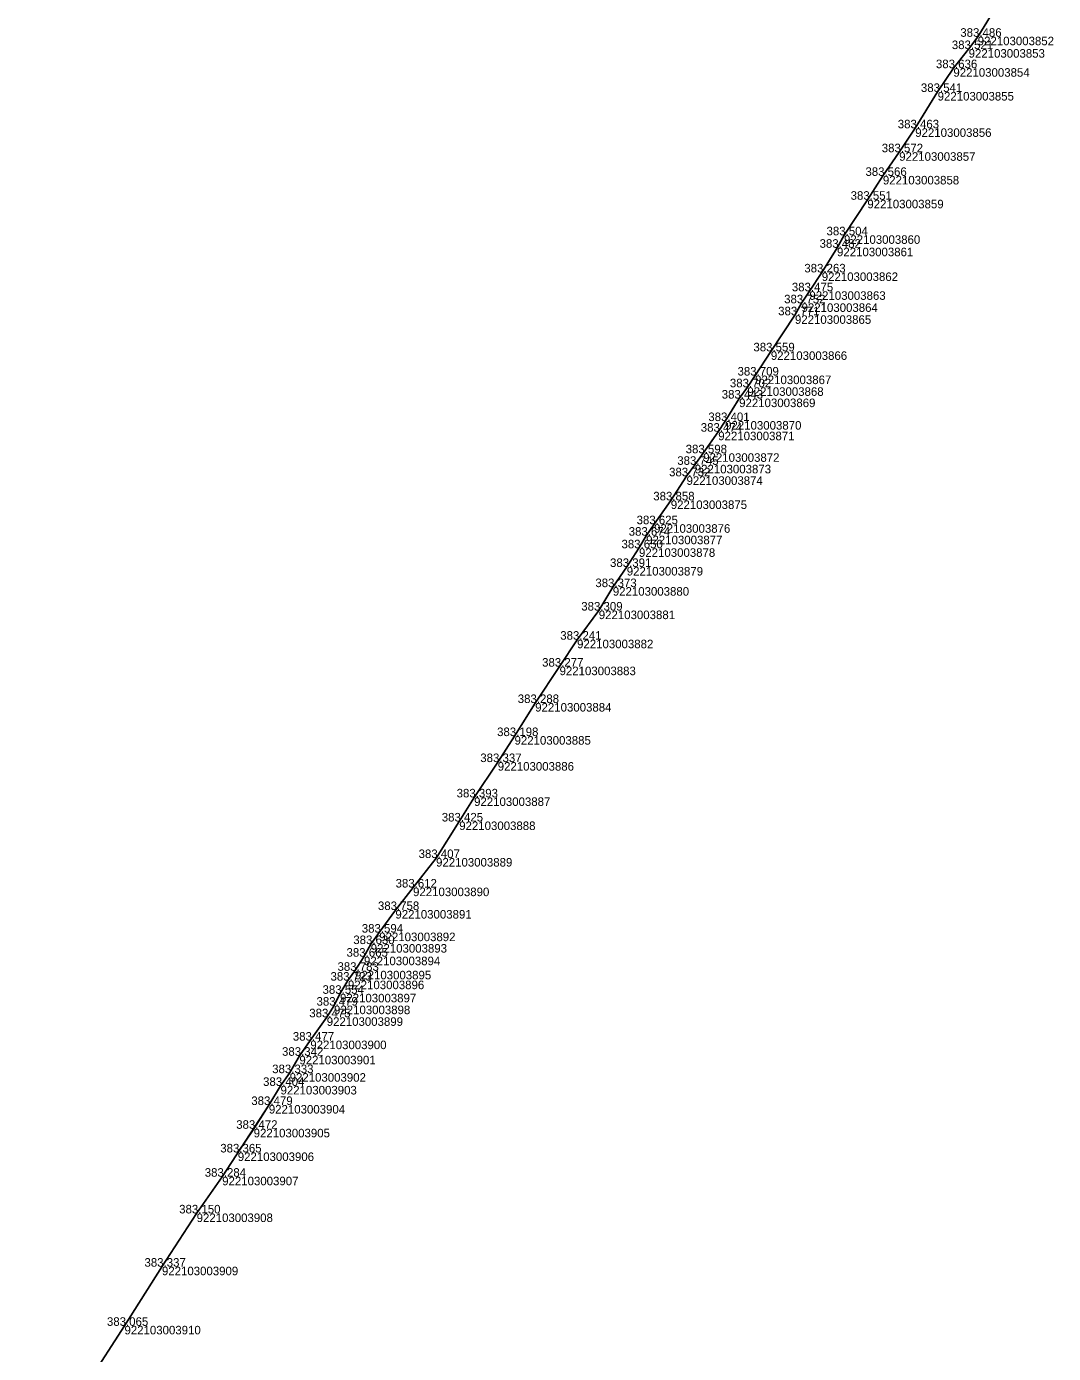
# Model space of a CAD drawing. Extents: x -771047 to -756200, y -1053876 to -1046520.
# Drawn here: x -756960.7 to -756816.5, y -1047253.2 to -1047067 of the extents above; entities that cross this region are included whole.
import ezdxf

# ---------------------------------------------------------------- set-up
doc = ezdxf.new("R2010")
doc.units = 0
for name, color, linetype in [('Vrstva 32', 7, 'Continuous'), ('Vrstva 60', 7, 'Continuous'), ('Vrstva 61', 7, 'Continuous')]:
    doc.layers.add(name, color=color, linetype=linetype)

msp = doc.modelspace()

# ---------------------------------------------------------------- linework, layer by layer
at = {"layer": 'Vrstva 32'}
for points in [[(-756825.38, -1047065.54), (-756827.16, -1047068.41), (-756828.44, -1047070.14), (-756830.58, -1047072.82), (-756832.79, -1047076.16), (-756835.94, -1047081.26), (-756838.19, -1047084.62), (-756840.48, -1047087.94), (-756842.66, -1047091.29), (-756845.94, -1047096.28), (-756846.92, -1047098.03)], [(-756846.92, -1047098.03), (-756849.06, -1047101.49), (-756850.8, -1047104.14)], [(-756850.8, -1047104.14), (-756851.9, -1047105.83), (-756852.83, -1047107.51), (-756856.21, -1047112.57), (-756858.43, -1047115.97), (-756859.51, -1047117.62), (-756860.66, -1047119.2)], [(-756860.66, -1047119.2), (-756862.63, -1047122.36), (-756863.6, -1047123.85), (-756865.71, -1047126.88)], [(-756865.71, -1047126.88), (-756866.89, -1047128.5), (-756868.05, -1047130.11), (-756870.26, -1047133.49), (-756872.61, -1047136.84), (-756873.72, -1047138.45), (-756874.73, -1047140.22)], [(-756874.73, -1047140.22), (-756876.44, -1047142.84), (-756878.4, -1047145.67), (-756880.37, -1047148.96), (-756883.42, -1047153.05), (-756885.88, -1047156.83), (-756889.3, -1047161.94), (-756892.2, -1047166.58), (-756894.56, -1047170.23)], [(-756894.56, -1047170.23), (-756897.88, -1047175.19), (-756899.97, -1047178.57), (-756903.22, -1047183.7)], [(-756903.22, -1047183.7), (-756906.45, -1047187.84)], [(-756906.45, -1047187.84), (-756908.93, -1047191)], [(-756908.93, -1047191), (-756911.2, -1047194.17)], [(-756911.2, -1047194.17), (-756912.39, -1047195.78), (-756913.34, -1047197.55), (-756914.61, -1047199.53), (-756915.59, -1047200.91), (-756916.71, -1047202.76), (-756917.55, -1047204.42), (-756918.57, -1047206.06), (-756920.88, -1047209.33)], [(-756920.88, -1047209.33), (-756922.41, -1047211.46), (-756923.78, -1047213.9), (-756925.06, -1047215.69), (-756926.7, -1047218.37), (-756933.25, -1047228.44), (-756936.84, -1047233.59), (-756941.71, -1047241.07), (-756946.97, -1047249.37), (-756951.98, -1047257.13), (-756957.27, -1047264.84), (-756960.72, -1047269.53)], [(-756926.7, -1047218.37), (-756928.83, -1047221.71), (-756931.06, -1047225.03)]]:
    msp.add_lwpolyline(points, dxfattribs=at)
at = {"layer": 'Vrstva 60'}
for p, q in [((-756827.16, -1047068.41), (-756827.16, -1047068.41)), ((-756828.44, -1047070.14), (-756828.44, -1047070.14)), ((-756830.58, -1047072.82), (-756830.58, -1047072.82)), ((-756832.79, -1047076.16), (-756832.79, -1047076.16)), ((-756835.94, -1047081.26), (-756835.94, -1047081.26)), ((-756838.19, -1047084.62), (-756838.19, -1047084.62)), ((-756840.48, -1047087.94), (-756840.48, -1047087.94)), ((-756842.66, -1047091.29), (-756842.66, -1047091.29)), ((-756845.94, -1047096.28), (-756845.94, -1047096.28)), ((-756846.92, -1047098.03), (-756846.92, -1047098.03)), ((-756849.06, -1047101.49), (-756849.06, -1047101.49)), ((-756850.8, -1047104.14), (-756850.8, -1047104.14)), ((-756852.83, -1047107.51), (-756852.83, -1047107.51)), ((-756851.9, -1047105.83), (-756851.9, -1047105.83)), ((-756856.21, -1047112.57), (-756856.21, -1047112.57)), ((-756858.43, -1047115.97), (-756858.43, -1047115.97)), ((-756859.51, -1047117.62), (-756859.51, -1047117.62)), ((-756860.66, -1047119.2), (-756860.66, -1047119.2)), ((-756862.63, -1047122.36), (-756862.63, -1047122.36)), ((-756863.6, -1047123.85), (-756863.6, -1047123.85)), ((-756865.71, -1047126.88), (-756865.71, -1047126.88)), ((-756866.89, -1047128.5), (-756866.89, -1047128.5)), ((-756868.05, -1047130.11), (-756868.05, -1047130.11)), ((-756870.26, -1047133.49), (-756870.26, -1047133.49)), ((-756872.61, -1047136.84), (-756872.61, -1047136.84)), ((-756873.72, -1047138.45), (-756873.72, -1047138.45)), ((-756874.73, -1047140.22), (-756874.73, -1047140.22)), ((-756876.44, -1047142.84), (-756876.44, -1047142.84)), ((-756878.4, -1047145.67), (-756878.4, -1047145.67)), ((-756880.37, -1047148.96), (-756880.37, -1047148.96)), ((-756883.42, -1047153.05), (-756883.42, -1047153.05)), ((-756885.88, -1047156.83), (-756885.88, -1047156.83)), ((-756889.3, -1047161.94), (-756889.3, -1047161.94)), ((-756892.2, -1047166.58), (-756892.2, -1047166.58)), ((-756894.56, -1047170.23), (-756894.56, -1047170.23)), ((-756897.88, -1047175.19), (-756897.88, -1047175.19)), ((-756899.97, -1047178.57), (-756899.97, -1047178.57)), ((-756903.22, -1047183.7), (-756903.22, -1047183.7)), ((-756906.45, -1047187.84), (-756906.45, -1047187.84)), ((-756908.93, -1047191), (-756908.93, -1047191)), ((-756911.2, -1047194.17), (-756911.2, -1047194.17)), ((-756912.39, -1047195.78), (-756912.39, -1047195.78)), ((-756913.34, -1047197.55), (-756913.34, -1047197.55)), ((-756914.61, -1047199.53), (-756914.61, -1047199.53)), ((-756915.59, -1047200.91), (-756915.59, -1047200.91)), ((-756917.55, -1047204.42), (-756917.55, -1047204.42)), ((-756916.71, -1047202.76), (-756916.71, -1047202.76)), ((-756918.57, -1047206.06), (-756918.57, -1047206.06)), ((-756920.88, -1047209.33), (-756920.88, -1047209.33)), ((-756922.41, -1047211.46), (-756922.41, -1047211.46)), ((-756925.06, -1047215.69), (-756925.06, -1047215.69)), ((-756923.78, -1047213.9), (-756923.78, -1047213.9)), ((-756926.7, -1047218.37), (-756926.7, -1047218.37)), ((-756928.83, -1047221.71), (-756928.83, -1047221.71)), ((-756931.06, -1047225.03), (-756931.06, -1047225.03)), ((-756933.25, -1047228.44), (-756933.25, -1047228.44)), ((-756936.84, -1047233.59), (-756936.84, -1047233.59)), ((-756941.71, -1047241.07), (-756941.71, -1047241.07)), ((-756946.97, -1047249.37), (-756946.97, -1047249.37))]:
    msp.add_line(p, q, dxfattribs=at)

# ---------------------------------------------------------------- texts
for s, p in [('922103003852', (-756827.16, -1047069.6)), ('922103003853', (-756828.44, -1047071.34)), ('922103003854', (-756830.58, -1047074.02)), ('922103003855', (-756832.79, -1047077.36)), ('922103003856', (-756835.94, -1047082.46)), ('922103003857', (-756838.19, -1047085.82)), ('922103003858', (-756840.48, -1047089.14)), ('922103003859', (-756842.66, -1047092.49)), ('922103003860', (-756845.94, -1047097.48)), ('922103003861', (-756846.92, -1047099.22)), ('922103003862', (-756849.06, -1047102.69)), ('922103003864', (-756851.9, -1047107.03)), ('922103003863', (-756850.8, -1047105.34)), ('922103003865', (-756852.83, -1047108.71)), ('922103003866', (-756856.21, -1047113.77)), ('922103003867', (-756858.43, -1047117.17)), ('922103003868', (-756859.51, -1047118.82)), ('922103003869', (-756860.66, -1047120.4)), ('922103003870', (-756862.63, -1047123.56)), ('922103003871', (-756863.6, -1047125.05)), ('922103003872', (-756865.71, -1047128.08)), ('922103003873', (-756866.89, -1047129.7)), ('922103003874', (-756868.05, -1047131.31)), ('922103003875', (-756870.26, -1047134.7)), ('922103003876', (-756872.61, -1047138.04)), ('922103003877', (-756873.72, -1047139.65)), ('922103003878', (-756874.73, -1047141.42)), ('922103003879', (-756876.44, -1047144.04)), ('922103003880', (-756878.4, -1047146.87)), ('922103003881', (-756880.37, -1047150.16)), ('922103003882', (-756883.42, -1047154.25)), ('922103003883', (-756885.88, -1047158.03)), ('922103003884', (-756889.3, -1047163.14)), ('922103003885', (-756892.2, -1047167.78)), ('922103003886', (-756894.56, -1047171.43)), ('922103003887', (-756897.88, -1047176.39)), ('922103003888', (-756899.97, -1047179.77)), ('922103003889', (-756903.22, -1047184.9)), ('922103003890', (-756906.45, -1047189.05)), ('922103003891', (-756908.93, -1047192.2)), ('922103003892', (-756911.2, -1047195.37)), ('922103003893', (-756912.39, -1047196.98)), ('922103003894', (-756913.34, -1047198.75)), ('922103003895', (-756914.61, -1047200.73)), ('922103003896', (-756915.59, -1047202.11)), ('922103003898', (-756917.55, -1047205.62)), ('922103003897', (-756916.71, -1047203.96)), ('922103003899', (-756918.57, -1047207.26)), ('922103003900', (-756920.88, -1047210.53)), ('922103003901', (-756922.41, -1047212.66)), ('922103003903', (-756925.06, -1047216.89)), ('922103003902', (-756923.78, -1047215.1)), ('922103003904', (-756926.7, -1047219.57)), ('922103003905', (-756928.83, -1047222.91)), ('922103003906', (-756931.06, -1047226.23)), ('922103003907', (-756933.25, -1047229.64)), ('922103003908', (-756936.84, -1047234.8)), ('922103003909', (-756941.71, -1047242.27)), ('922103003910', (-756946.97, -1047250.57))]:
    msp.add_text(s, height=1.2, dxfattribs=at).set_placement(p)
at = {"layer": 'Vrstva 61'}
for s, p in [('383.486', (-756829.61, -1047068.41)), ('383.521', (-756830.8, -1047070.14)), ('383.636', (-756833.03, -1047072.82)), ('383.541', (-756835.14, -1047076.16)), ('383.463', (-756838.39, -1047081.26)), ('383.572', (-756840.64, -1047084.62)), ('383.566', (-756842.93, -1047087.94)), ('383.551', (-756845.01, -1047091.29)), ('383.504', (-756848.39, -1047096.28)), ('383.482', (-756849.37, -1047098.03)), ('383.263', (-756851.51, -1047101.49)), ('383.475', (-756853.26, -1047104.14)), ('383.752', (-756854.34, -1047105.83)), ('383.771', (-756855.18, -1047107.51)), ('383.559', (-756858.66, -1047112.57)), ('383.709', (-756860.89, -1047115.97)), ('383.702', (-756861.96, -1047117.62)), ('383.443', (-756863.11, -1047119.2)), ('383.401', (-756864.99, -1047122.36)), ('383.474', (-756866.05, -1047123.85)), ('383.598', (-756868.17, -1047126.88)), ('383.745', (-756869.35, -1047128.5)), ('383.732', (-756870.5, -1047130.11)), ('383.858', (-756872.72, -1047133.49)), ('383.625', (-756875.06, -1047136.84)), ('383.674', (-756876.17, -1047138.45)), ('383.650', (-756877.18, -1047140.22)), ('383.391', (-756878.79, -1047142.84)), ('383.373', (-756880.85, -1047145.67)), ('383.309', (-756882.83, -1047148.96)), ('383.241', (-756885.78, -1047153.05)), ('383.277', (-756888.33, -1047156.83)), ('383.288', (-756891.75, -1047161.94)), ('383.198', (-756894.65, -1047166.58)), ('383.337', (-756897.01, -1047170.23)), ('383.393', (-756900.33, -1047175.19)), ('383.425', (-756902.42, -1047178.57)), ('383.407', (-756905.67, -1047183.7)), ('383.612', (-756908.9, -1047187.84)), ('383.758', (-756911.38, -1047191)), ('383.594', (-756913.65, -1047194.17)), ('383.630', (-756914.84, -1047195.78)), ('383.665', (-756915.79, -1047197.55)), ('383.783', (-756917.06, -1047199.53)), ('383.723', (-756918.04, -1047200.91)), ('383.554', (-756919.16, -1047202.76)), ('383.479', (-756920, -1047204.42)), ('383.475', (-756921.02, -1047206.06)), ('383.477', (-756923.33, -1047209.33)), ('383.342', (-756924.85, -1047211.46)), ('383.333', (-756926.23, -1047213.9)), ('383.404', (-756927.51, -1047215.69)), ('383.479', (-756929.16, -1047218.37)), ('383.472', (-756931.28, -1047221.71)), ('383.365', (-756933.52, -1047225.03)), ('383.284', (-756935.7, -1047228.44)), ('383.150', (-756939.29, -1047233.59)), ('383.337', (-756944.16, -1047241.07)), ('383.065', (-756949.43, -1047249.37))]:
    msp.add_text(s, height=1.2, dxfattribs=at).set_placement(p)

doc.saveas('drawing.dxf')
